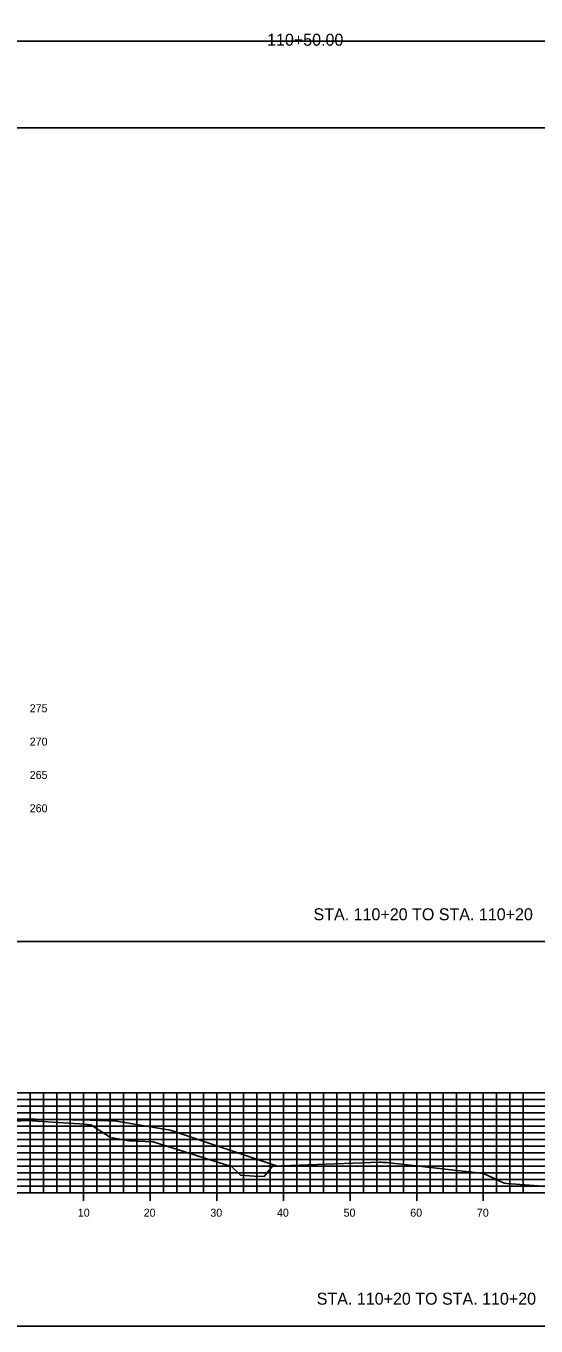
# Model space of a CAD drawing. Extents: x 1661012 to 1662122, y 670053 to 671852.
# Drawn here: x 1661908.9 to 1661985.4, y 671480 to 671675 of the extents above; entities that cross this region are included whole.
import ezdxf

# ---------------------------------------------------------------- set-up
doc = ezdxf.new("R2010")
doc.units = 0
for name, color, linetype in [('R_Concrete', 7, 'Continuous'), ('R_Concrete Hidden', 7, 'Continuous'), ('R_Erosion', 7, 'Continuous'), ('R_Exist Surface', 7, 'Continuous'), ('R_Proposed Road', 7, 'Continuous'), ('R_ROW Annot', 7, 'Continuous')]:
    doc.layers.add(name, color=color, linetype=linetype)

msp = doc.modelspace()

# ---------------------------------------------------------------- linework, layer by layer
at = {"layer": 'R_Concrete'}
for p, q in [((1661707.5, 671514.96), (1662037.5, 671514.96)), ((1661909.5, 671499.96), (1661909.5, 671514.96)), ((1661911.5, 671499.96), (1661911.5, 671514.96)), ((1661913.5, 671499.96), (1661913.5, 671514.96)), ((1661915.5, 671499.96), (1661915.5, 671514.96)), ((1661917.5, 671499.96), (1661917.5, 671514.96)), ((1661919.5, 671499.96), (1661919.5, 671514.96)), ((1661921.5, 671499.96), (1661921.5, 671514.96)), ((1661923.5, 671499.96), (1661923.5, 671514.96)), ((1661925.5, 671499.96), (1661925.5, 671514.96)), ((1661927.5, 671499.96), (1661927.5, 671514.96)), ((1661929.5, 671499.96), (1661929.5, 671514.96)), ((1661931.5, 671499.96), (1661931.5, 671514.96)), ((1661933.5, 671499.96), (1661933.5, 671514.96)), ((1661935.5, 671499.96), (1661935.5, 671514.96)), ((1661937.5, 671499.96), (1661937.5, 671514.96)), ((1661939.5, 671499.96), (1661939.5, 671514.96)), ((1661941.5, 671499.96), (1661941.5, 671514.96)), ((1661943.5, 671499.96), (1661943.5, 671514.96)), ((1661945.5, 671499.96), (1661945.5, 671514.96)), ((1661947.5, 671499.96), (1661947.5, 671514.96)), ((1661949.5, 671499.96), (1661949.5, 671514.96)), ((1661951.5, 671499.96), (1661951.5, 671514.96)), ((1661953.5, 671499.96), (1661953.5, 671514.96)), ((1661955.5, 671499.96), (1661955.5, 671514.96)), ((1661957.5, 671499.96), (1661957.5, 671514.96)), ((1661959.5, 671499.96), (1661959.5, 671514.96)), ((1661961.5, 671499.96), (1661961.5, 671514.96)), ((1661963.5, 671499.96), (1661963.5, 671514.96)), ((1661965.5, 671499.96), (1661965.5, 671514.96)), ((1661967.5, 671499.96), (1661967.5, 671514.96)), ((1661969.5, 671499.96), (1661969.5, 671514.96)), ((1661971.5, 671499.96), (1661971.5, 671514.96)), ((1661973.5, 671499.96), (1661973.5, 671514.96)), ((1661975.5, 671499.96), (1661975.5, 671514.96)), ((1661977.5, 671499.96), (1661977.5, 671514.96)), ((1661979.5, 671499.96), (1661979.5, 671514.96)), ((1661981.5, 671499.96), (1661981.5, 671514.96)), ((1661983.5, 671499.96), (1661983.5, 671514.96)), ((1661707.5, 671513.96), (1662037.5, 671513.96)), ((1661707.5, 671512.96), (1662037.5, 671512.96)), ((1661707.5, 671511.96), (1662037.5, 671511.96)), ((1661707.5, 671510.96), (1662037.5, 671510.96)), ((1661707.5, 671509.96), (1662037.5, 671509.96)), ((1661707.5, 671508.96), (1662037.5, 671508.96)), ((1661707.5, 671507.96), (1662037.5, 671507.96)), ((1661707.5, 671506.96), (1662037.5, 671506.96)), ((1661707.5, 671505.96), (1662037.5, 671505.96)), ((1661707.5, 671504.96), (1662037.5, 671504.96)), ((1661707.5, 671503.96), (1662037.5, 671503.96)), ((1661707.5, 671502.96), (1662037.5, 671502.96)), ((1661707.5, 671501.96), (1662037.5, 671501.96)), ((1661707.5, 671500.96), (1662037.5, 671500.96)), ((1661909.5, 671499.96), (1661909.5, 671500.56)), ((1661911.5, 671499.96), (1661911.5, 671500.56)), ((1661913.5, 671499.96), (1661913.5, 671500.56)), ((1661915.5, 671499.96), (1661915.5, 671500.56)), ((1661917.5, 671498.76), (1661917.5, 671501.16)), ((1661919.5, 671499.96), (1661919.5, 671500.56)), ((1661921.5, 671499.96), (1661921.5, 671500.56)), ((1661923.5, 671499.96), (1661923.5, 671500.56)), ((1661925.5, 671499.96), (1661925.5, 671500.56)), ((1661927.5, 671498.76), (1661927.5, 671501.16)), ((1661929.5, 671499.96), (1661929.5, 671500.56)), ((1661931.5, 671499.96), (1661931.5, 671500.56)), ((1661933.5, 671499.96), (1661933.5, 671500.56)), ((1661935.5, 671499.96), (1661935.5, 671500.56)), ((1661937.5, 671498.76), (1661937.5, 671501.16)), ((1661939.5, 671499.96), (1661939.5, 671500.56)), ((1661941.5, 671499.96), (1661941.5, 671500.56)), ((1661943.5, 671499.96), (1661943.5, 671500.56)), ((1661945.5, 671499.96), (1661945.5, 671500.56)), ((1661947.5, 671498.76), (1661947.5, 671501.16)), ((1661949.5, 671499.96), (1661949.5, 671500.56)), ((1661951.5, 671499.96), (1661951.5, 671500.56)), ((1661953.5, 671499.96), (1661953.5, 671500.56)), ((1661955.5, 671499.96), (1661955.5, 671500.56)), ((1661957.5, 671498.76), (1661957.5, 671501.16)), ((1661959.5, 671499.96), (1661959.5, 671500.56)), ((1661961.5, 671499.96), (1661961.5, 671500.56)), ((1661963.5, 671499.96), (1661963.5, 671500.56)), ((1661965.5, 671499.96), (1661965.5, 671500.56)), ((1661967.5, 671498.76), (1661967.5, 671501.16)), ((1661969.5, 671499.96), (1661969.5, 671500.56)), ((1661971.5, 671499.96), (1661971.5, 671500.56)), ((1661973.5, 671499.96), (1661973.5, 671500.56)), ((1661975.5, 671499.96), (1661975.5, 671500.56)), ((1661977.5, 671498.76), (1661977.5, 671501.16)), ((1661979.5, 671499.96), (1661979.5, 671500.56)), ((1661981.5, 671499.96), (1661981.5, 671500.56)), ((1661983.5, 671499.96), (1661983.5, 671500.56)), ((1661707.5, 671499.96), (1662037.5, 671499.96))]:
    msp.add_line(p, q, dxfattribs=at)
at = {"layer": 'R_Erosion'}
msp.add_lwpolyline([(1661899.87, 671510.24), (1661908.94, 671510.8), (1661916.91, 671510.28), (1661918.61, 671510.16), (1661921.53, 671508.23), (1661924.34, 671507.75), (1661927.95, 671507.59), (1661927.97, 671507.57), (1661938.58, 671504.26), (1661939.41, 671503.99), (1661939.71, 671503.92), (1661939.72, 671503.91), (1661941.04, 671502.57), (1661943.11, 671502.45), (1661944.59, 671502.4), (1661945.41, 671503.37), (1661945.85, 671503.93), (1661961.98, 671504.53), (1661962.13, 671504.55), (1661962.41, 671504.5), (1661962.95, 671504.47), (1661977.55, 671502.83), (1661980.65, 671501.41), (1661980.73, 671501.37), (1661981.01, 671501.35), (1661989.09, 671500.73)], dxfattribs=at)
at = {"layer": 'R_Exist Surface'}
msp.add_line((1661707.5, 671499.96), (1662037.5, 671499.96), dxfattribs=at)
at = {"layer": 'R_Proposed Road'}
for points in [[(1661756.99, 671659.7), (1662116.99, 671659.7), (1662116.99, 671852.4), (1661756.99, 671852.4)], [(1661677.02, 671537.62), (1662037.02, 671537.62), (1662037.02, 671730.32), (1661677.02, 671730.32)], [(1661677.5, 671479.96), (1662037.5, 671479.96), (1662037.5, 671672.66), (1661677.5, 671672.66)]]:
    msp.add_lwpolyline(points, close=True, dxfattribs=at)
at = {"layer": 'R_ROW Annot'}
msp.add_lwpolyline([(1661809.1, 671506.8), (1661826.43, 671501.02), (1661853, 671509.88), (1661885.09, 671510.52), (1661892.5, 671510.67), (1661896.5, 671510.83), (1661907.5, 671511.05), (1661918.5, 671510.83), (1661922.5, 671510.67), (1661929.91, 671509.43), (1661930.5, 671509.34), (1661946.62, 671503.96)], dxfattribs=at)

# ---------------------------------------------------------------- texts
at = {"layer": 'R_Concrete Hidden'}
for s, height, p in [('110+50.00', 1.8, (1661945.05, 671672)), ('275', 1.2, (1661909.42, 671572.02)), ('270', 1.2, (1661909.42, 671567.02)), ('265', 1.2, (1661909.42, 671562.02)), ('260', 1.2, (1661909.42, 671557.02)), ('STA. 110+20 TO STA. 110+20', 1.8, (1661952.02, 671540.82)), ('10', 1.2, (1661916.64, 671496.36)), ('20', 1.2, (1661926.53, 671496.36)), ('30', 1.2, (1661936.53, 671496.36)), ('40', 1.2, (1661946.53, 671496.36)), ('50', 1.2, (1661956.53, 671496.36)), ('60', 1.2, (1661966.53, 671496.36)), ('70', 1.2, (1661976.53, 671496.36)), ('STA. 110+20 TO STA. 110+20', 1.8, (1661952.5, 671483.16)), ('STA. 110+20 TO STA. 110+20', 1.8, (1661952.5, 671483.16))]:
    msp.add_text(s, height=height, dxfattribs=at).set_placement(p)

doc.saveas('drawing.dxf')
